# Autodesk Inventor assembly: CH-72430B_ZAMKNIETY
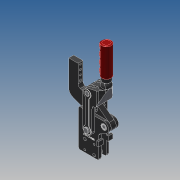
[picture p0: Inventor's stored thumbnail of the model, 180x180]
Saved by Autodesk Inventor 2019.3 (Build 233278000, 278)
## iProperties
Company: Î¢ÈíÖÐ¹ú
Created: 2012-10
Part Number: CH-72430B_ZAMKNIETY
Material: Ogólny
Description: STEP AP203
Document SubType Name: Assembly
Designer: CADENGINEERING4
Sending System: SolidWorks 2010
Preprocessor: SwSTEP 2.0
Title: CH-72430B.STEP
Author: Î¢ÈíÓÃ»§
Revision Number: ÈÎºÎ
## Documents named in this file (12)
- E:\CAD_CLAMPS\Heavy duty weldables\CH-72430B_DODAC\CH-72430B_ZAMKNIETY.iam
- E:\CAD_CLAMPS\Heavy duty weldables\CH-72430B_DODAC\72425-06.ipt
- E:\CAD_CLAMPS\Heavy duty weldables\CH-72430B_DODAC\CH-72430B-01.ipt
- E:\CAD_CLAMPS\Heavy duty weldables\CH-72430B_DODAC\72425-09.ipt
- E:\CAD_CLAMPS\Heavy duty weldables\CH-72430B_DODAC\72425-04.ipt
- E:\CAD_CLAMPS\Heavy duty weldables\CH-72430B_DODAC\72425-07.ipt
- E:\CAD_CLAMPS\Heavy duty weldables\CH-72430B_DODAC\72425-08.ipt
- E:\CAD_CLAMPS\Heavy duty weldables\CH-72430B_DODAC\M12.ipt
- E:\CAD_CLAMPS\Heavy duty weldables\CH-72430B_DODAC\72425-10.ipt
- E:\CAD_CLAMPS\Heavy duty weldables\CH-72430B_DODAC\72425-11.ipt
- E:\CAD_CLAMPS\Heavy duty weldables\CH-72430B_DODAC\CH-72430B-02.ipt
- E:\CAD_CLAMPS\Heavy duty weldables\CH-72430B_DODAC\72425-03.ipt
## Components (20 placed, 20 different names)
1. 72425-06_1 — Zestawiające:14, Równoległe:3
2. 72425-06_2 — Zestawiające:19, Równoległe:6
3. 72425-06_3 — Zestawiające:21, Równoległe:8, Zestawiające:23, Zestawiające:27
4. CH-72430B-01_4 — Zestawiające:18, Równoległe:5, Zestawiające:19, Równoległe:6, Równoległe:7, Zestawiające:21, Równoległe:8, Zestawiające:22, Równoległe:9, Zestawiające:24, Zestawiające:26, Kątowe:1
5. 72425-06_5 — Zestawiające:13, Równoległe:2, Zestawiające:15
6. 72425-09_6 — Zestawiające:23, Zestawiające:24
7. 72425-06_7 — Zestawiające:18, Równoległe:5, Zestawiające:20
8. 72425-04_8 — Zestawiające:1, Zestawiające:3, Zestawiające:4, Zestawiające:5, Zestawiające:6, Zestawiające:12, Równoległe:1, Zestawiające:27, Zestawiające:28, Zestawiające:29, Zestawiające:31, Zestawiające:32
9. 72425-07_9 — Zestawiające:12, Równoległe:1
10. 72425-06_10 — Zestawiające:8, Zestawiające:9
11. 72425-08_11 — Zestawiające:15, Równoległe:4, Zestawiające:17
12. M12_12 — Zestawiające:30, Zestawiające:31
13. 72425-10_13 — Zestawiające:28, Zestawiające:29, Zestawiające:30
14. 72425-11_14 — Zestawiające:1, Zestawiające:32, Kątowe:2
15. CH-72430B-02_15 — Zestawiające:16, Zestawiające:17, Zestawiające:25, Zestawiające:26, Kątowe:1, Kątowe:2
16. 72425-06_16 — Zestawiające:22, Równoległe:9
17. 72425-08_17 — Zestawiające:20, Równoległe:7, Zestawiające:25
18. 72425-03_18 — Zestawiające:3, Zestawiające:4, Zestawiające:7, Zestawiające:10, Zestawiające:11, Zestawiające:13, Równoległe:2, Równoległe:4, Zestawiające:16
19. 72425-03_19 — Zestawiające:5, Zestawiające:6, Zestawiające:7, Zestawiające:8, Zestawiające:9, Zestawiające:14, Równoległe:3
20. 72425-06_20 — Zestawiające:10, Zestawiające:11
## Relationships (42: Mate 31, Flush 9, Angle 2)
- Zestawiające:1 [Mate]: 72425-04_8 ↔ 72425-11_14
- Zestawiające:3 [Mate]: 72425-04_8 ↔ 72425-03_18
- Zestawiające:4 [Mate]: 72425-04_8 ↔ 72425-03_18
- Zestawiające:5 [Mate]: 72425-04_8 ↔ 72425-03_19
- Zestawiające:6 [Mate]: 72425-04_8 ↔ 72425-03_19
- Zestawiające:7 [Mate]: 72425-03_18 ↔ 72425-03_19
- Zestawiające:8 [Mate]: 72425-06_10 ↔ 72425-03_19
- Zestawiające:9 [Mate]: 72425-06_10 ↔ 72425-03_19
- Zestawiające:10 [Mate]: 72425-03_18 ↔ 72425-06_20
- Zestawiające:11 [Mate]: 72425-03_18 ↔ 72425-06_20
- Zestawiające:12 [Mate]: 72425-04_8 ↔ 72425-07_9
- Równoległe:1 [Flush]: 72425-04_8 ↔ 72425-07_9
- Zestawiające:13 [Mate]: 72425-06_5 ↔ 72425-03_18
- Zestawiające:14 [Mate]: 72425-06_1 ↔ 72425-03_19
- Równoległe:2 [Flush]: 72425-06_5 ↔ 72425-03_18
- Równoległe:3 [Flush]: 72425-06_1 ↔ 72425-03_19
- Zestawiające:15 [Mate]: 72425-06_5 ↔ 72425-08_11
- Równoległe:4 [Flush]: 72425-08_11 ↔ 72425-03_18
- Zestawiające:16 [Mate]: CH-72430B-02_15 ↔ 72425-03_18
- Zestawiające:17 [Mate]: 72425-08_11 ↔ CH-72430B-02_15
- Zestawiające:18 [Mate]: CH-72430B-01_4 ↔ 72425-06_7
- Równoległe:5 [Flush]: CH-72430B-01_4 ↔ 72425-06_7
- Zestawiające:19 [Mate]: 72425-06_2 ↔ CH-72430B-01_4
- Równoległe:6 [Flush]: 72425-06_2 ↔ CH-72430B-01_4
- Zestawiające:20 [Mate]: 72425-06_7 ↔ 72425-08_17
- Równoległe:7 [Flush]: CH-72430B-01_4 ↔ 72425-08_17
- Zestawiające:21 [Mate]: 72425-06_3 ↔ CH-72430B-01_4
- Równoległe:8 [Flush]: 72425-06_3 ↔ CH-72430B-01_4
- Zestawiające:22 [Mate]: CH-72430B-01_4 ↔ 72425-06_16
- Równoległe:9 [Flush]: CH-72430B-01_4 ↔ 72425-06_16
- Zestawiające:23 [Mate]: 72425-06_3 ↔ 72425-09_6
- Zestawiające:24 [Mate]: CH-72430B-01_4 ↔ 72425-09_6
- Zestawiające:25 [Mate]: CH-72430B-02_15 ↔ 72425-08_17
- Zestawiające:26 [Mate]: CH-72430B-01_4 ↔ CH-72430B-02_15
- Zestawiające:27 [Mate]: 72425-06_3 ↔ 72425-04_8
- Zestawiające:28 [Mate]: 72425-04_8 ↔ 72425-10_13
- Zestawiające:29 [Mate]: 72425-04_8 ↔ 72425-10_13
- Zestawiające:30 [Mate]: M12_12 ↔ 72425-10_13
- Zestawiające:31 [Mate]: 72425-04_8 ↔ M12_12
- Zestawiające:32 [Mate]: 72425-04_8 ↔ 72425-11_14
- Kątowe:1 [Angle]: CH-72430B-01_4 ↔ CH-72430B-02_15
- Kątowe:2 [Angle]: 72425-11_14 ↔ CH-72430B-02_15
